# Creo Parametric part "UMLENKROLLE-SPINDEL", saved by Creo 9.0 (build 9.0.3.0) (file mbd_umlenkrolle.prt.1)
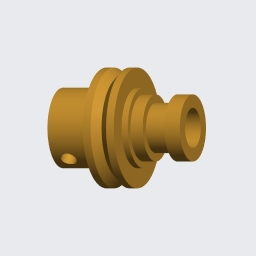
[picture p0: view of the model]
Units: millimeter Kilogram Sec (mmKs); MM, KILOGRAM, SECS
Materials in the file: STAHL

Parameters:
  WERKSTOFF = "Stahl"
  ERSTELLER = "ARINDA"
  BENENNUNG = "XXX"
  TEILETYP = "K"
  PTC_MASTER_MATERIAL = "STAHL"
  SCHRAUBEN_GROESSE = "M3x.5"
  METRISCH = "JA"

Other parameters: MASSE, STEIGUNG, BOHR_DURCHM, GEWINDEDURCHMESSER, GEWINDEGÄNGE_PRO_INCH, GEWINDETIEFE, GEWINDELÄNGE

Created from: ARINDA_STARTTEIL.PRT

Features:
  1. coordinate system
  2. datum plane "RECHTS_Y-Z"
  3. datum plane "OBEN_X-Z"
  4. datum plane "VORNE_X-Y"
  5. datum axis
  6. datum axis
  7. datum axis
  8. datum point "PNT0"
  9. revolve "Drehen 1"
  10. hole "Bohrung 1"
  11. extrusion "Profil 1"

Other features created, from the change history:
  coordinate system "CS1"

Other named items: LOGO, A_X, A_Y, A_Z, CS0

Layers: 01_ACHSEN, 01_ACHSEN_STD, 01_EBENEN_STD, 01_KOORDSYS_STD, 01_PUNKTE_STD, GEWINDE, SAMMELFLÄCHEN, VOLUMENGEOMETRIE

Notes: M3x.5 | GEWINDEBOHREN | 4.000 |  BOHREN (  | 2.500 | DURCH |   -(  |  ) BOHRUNG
